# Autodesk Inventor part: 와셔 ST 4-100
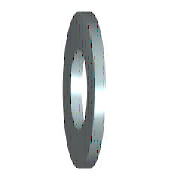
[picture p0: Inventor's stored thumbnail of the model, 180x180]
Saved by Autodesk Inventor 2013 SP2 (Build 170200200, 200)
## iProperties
IsCustomPart: 0
Created: 2012-02
Part Number: 와셔 ST 4-100
Material: 일반
Description: 평면 와셔 - 일반 시리즈 - 제품 등급 C
Document SubType Name: Modeling
Standard: ISO 7091
Designer: mduedu
Standard Revision: Second edition 2000-06-01
Standards Organization: ISO
Language: ko-KR
Size Designation: ST 4 - 100 HV
Categories: <MemberInstance><Categories><Category DisplayName="조임쇠" InternalName="e4da775c-781d-43d5-af7c-5136215cf5a6" Mnemonic="FSTN"><Category DisplayName="와셔" InternalN
Density: 1 g/cm^3
Mass: 0.0626355 g
Surface Area: 1.70824 cm^2
Volume: 0.0626355 cm^3
Author: mduedu
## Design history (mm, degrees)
sketch "스케치"
  geometry: C1 r 5 at (0, 0); C2 r 2.25 at (0, 0); 1 further point
  constraints: 2 centre point, 2 coincident
  dimensions: "d0" = 4.5 diameter of C2 (= SD1); "d1" = 10 diameter of C1 (= SD2)
extrude "본체" new body sketch "스케치" distance "d2" = 1 (= SD); taper "d3" = 0 deg
workaxis "Work Axis1"
workplane "Work Plane1"
body "Solid1"
other parameters: "SD1" = 4.5 [user parameter; used in 1 equation term], "SD2" = 10 [user parameter; used in 1 equation term], "SD" = 1 [user parameter; used in 1 equation term], "d4" = 0, "d5" = 0, "d6" = 0, "d7" = 0, "NND" = 4 [user parameter]
